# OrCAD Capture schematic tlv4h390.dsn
size A
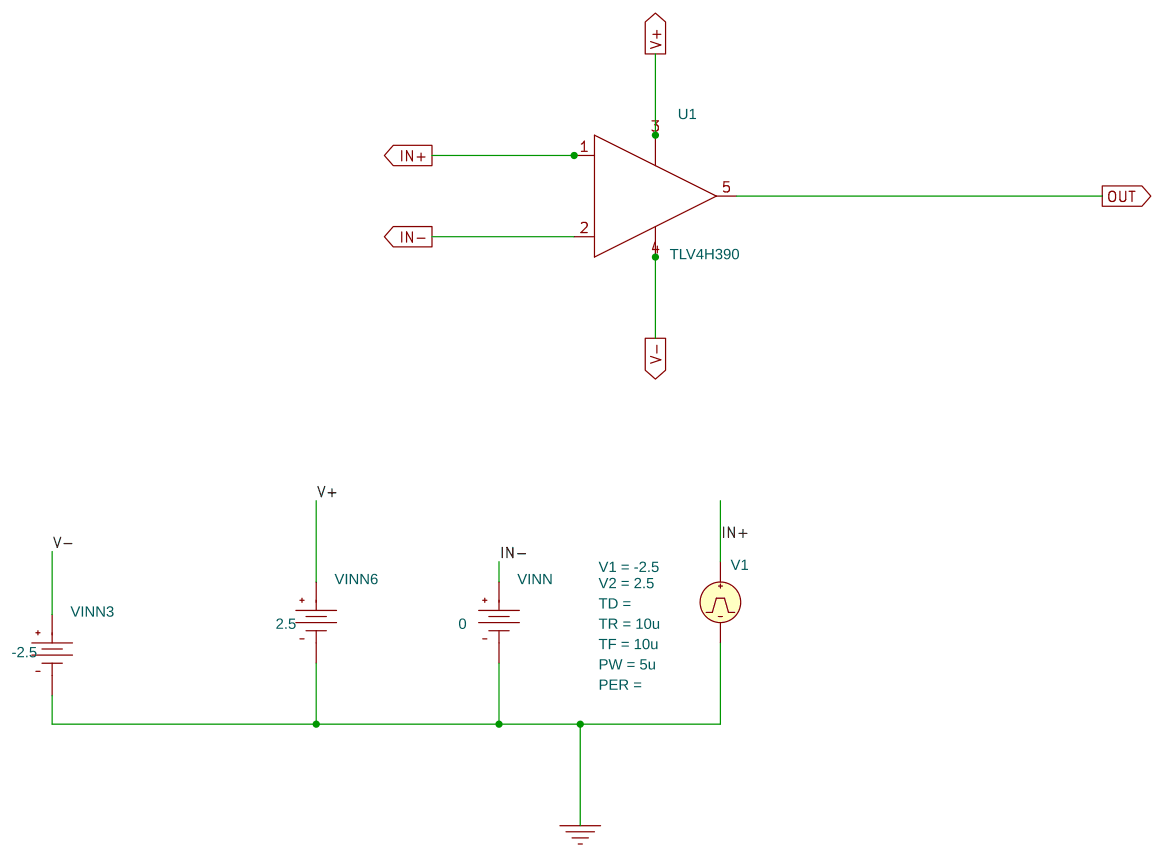
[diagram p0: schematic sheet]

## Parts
U1  TLV4H390
V1  VPULSE
VINN  VDC
VINN3  VDC
VINN6  VDC

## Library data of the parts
U1 = TLV4H390
V1 = VPULSE: PW: 5u; TF: 10u; TR: 10u; V1: -2.5; V2: 2.5
VINN = VDC: DC: 0
VINN3 = VDC: DC: -2.5
VINN6 = VDC: DC: 2.5

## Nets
0: V1.2(-) VINN.1(-) VINN3.1(-) VINN6.1(-)
IN+: U1.1(IN+) V1.1(+)
IN-: U1.2(IN-) VINN.0(+)
OUT: U1.5(OUT)
V+: U1.3(V+) VINN6.0(+)
V-: U1.4(V-) VINN3.0(+)
